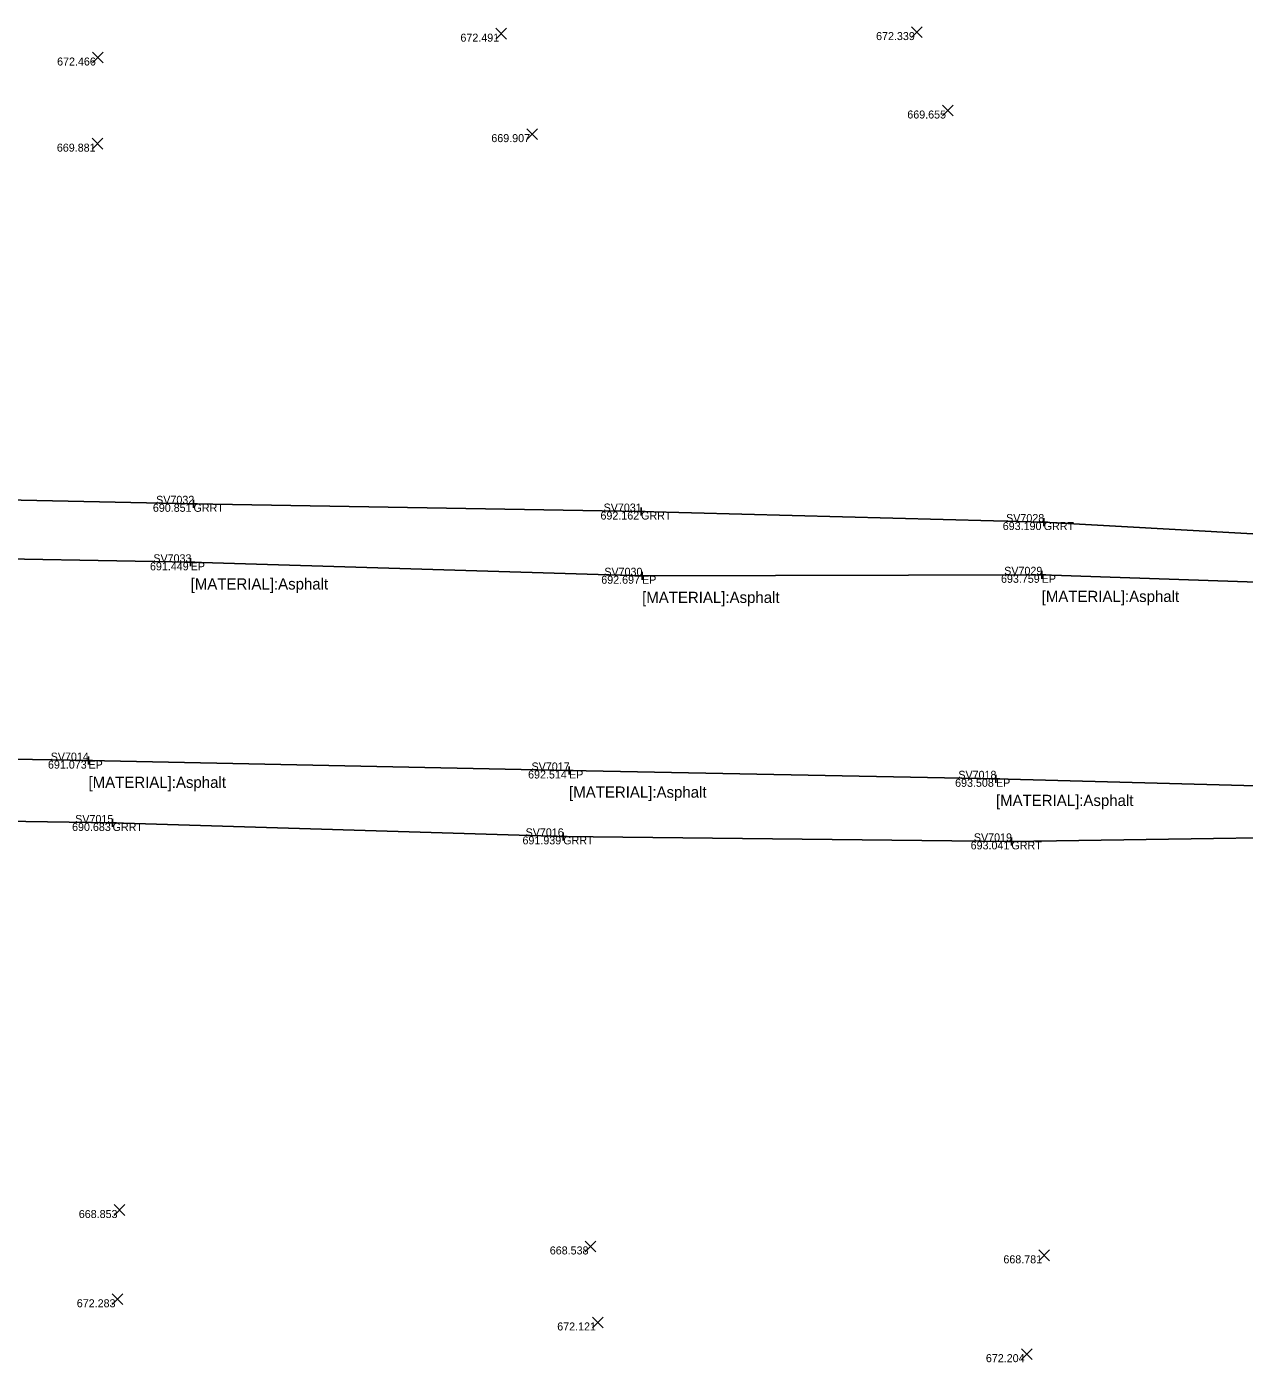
# Model space of a CAD drawing. Extents: x 1660019 to 1662995, y 619975 to 620342.
# Drawn here: x 1660960.5 to 1661112.6, y 620152.2 to 620319.1 of the extents above; entities that cross this region are included whole.
import ezdxf

# ---------------------------------------------------------------- set-up
doc = ezdxf.new("R2010")
doc.units = 0
for name, color, linetype in [('BR_X_Rail_Object', 7, 'Continuous'), ('PV_X_EOP', 7, 'Continuous'), ('RD_P_GR_Lt', 7, 'Continuous'), ('RD_P_GR_Rt', 7, 'Continuous'), ('RD_X_GR_Bar', 7, 'Continuous'), ('RD_X_GR_Rt', 7, 'Continuous'), ('RD_X_Wall', 7, 'Continuous'), ('SV_X_Text', 7, 'Continuous')]:
    doc.layers.add(name, color=color, linetype=linetype)

msp = doc.modelspace()

# ---------------------------------------------------------------- linework, layer by layer
at = {"layer": 'PV_X_EOP'}
for points in [[(1661208.92, 620246.9), (1661156.94, 620248.21), (1661087.29, 620250.6), (1661037.39, 620250.48), (1660981.01, 620252.16), (1660916.41, 620253.34), (1660855.2, 620254.44), (1660801.44, 620255.57), (1660749.64, 620256.49), (1660700.03, 620257.78), (1660643.44, 620258.64), (1660593.17, 620259.57)], [(1660597.37, 620234.1), (1660651.64, 620233.44), (1660703.42, 620232.61), (1660757.32, 620231.35), (1660809.76, 620230.12), (1660857.03, 620229.26), (1660910.07, 620228.44), (1660968.25, 620227.38), (1661028.27, 620226.15), (1661081.58, 620225.11), (1661140.41, 620223.53), (1661201.71, 620222.7)]]:
    msp.add_lwpolyline(points, dxfattribs=at)
at = {"layer": 'RD_P_GR_Lt'}
for p, q in [((1660980.87, 620259.47), (1660981.87, 620259.47)), ((1660981.37, 620259.97), (1660981.37, 620258.97)), ((1660981.37, 620259.47), (1660981.37, 620259.47)), ((1661037.26, 620259), (1661037.26, 620258)), ((1661036.76, 620258.5), (1661037.76, 620258.5)), ((1661037.26, 620258.5), (1661037.26, 620258.5)), ((1661087.04, 620257.19), (1661088.04, 620257.19)), ((1661087.54, 620257.69), (1661087.54, 620256.69)), ((1661087.54, 620257.19), (1661087.54, 620257.19)), ((1660980.51, 620252.16), (1660981.51, 620252.16)), ((1660981.01, 620252.66), (1660981.01, 620251.66)), ((1660981.01, 620252.16), (1660981.01, 620252.16)), ((1661036.89, 620250.48), (1661037.89, 620250.48)), ((1661037.39, 620250.98), (1661037.39, 620249.98)), ((1661037.39, 620250.48), (1661037.39, 620250.48)), ((1661086.79, 620250.6), (1661087.79, 620250.6)), ((1661087.29, 620251.1), (1661087.29, 620250.1)), ((1661087.29, 620250.6), (1661087.29, 620250.6)), ((1660967.75, 620227.38), (1660968.75, 620227.38)), ((1660968.25, 620227.88), (1660968.25, 620226.88)), ((1660968.25, 620227.38), (1660968.25, 620227.38)), ((1661027.77, 620226.15), (1661028.77, 620226.15)), ((1661028.27, 620226.65), (1661028.27, 620225.65)), ((1661028.27, 620226.15), (1661028.27, 620226.15)), ((1661081.58, 620225.61), (1661081.58, 620224.61)), ((1661081.08, 620225.11), (1661082.08, 620225.11)), ((1661081.58, 620225.11), (1661081.58, 620225.11)), ((1660970.76, 620219.59), (1660971.76, 620219.59)), ((1660971.26, 620220.09), (1660971.26, 620219.09)), ((1660971.26, 620219.59), (1660971.26, 620219.59)), ((1661027.04, 620217.92), (1661028.04, 620217.92)), ((1661027.54, 620218.42), (1661027.54, 620217.42)), ((1661027.54, 620217.92), (1661027.54, 620217.92)), ((1661083.01, 620217.29), (1661084.01, 620217.29)), ((1661083.51, 620217.79), (1661083.51, 620216.79)), ((1661083.51, 620217.29), (1661083.51, 620217.29))]:
    msp.add_line(p, q, dxfattribs=at)
at = {"layer": 'RD_P_GR_Rt'}
for p, q in [((1661019.12, 620317.54), (1661020.45, 620318.88)), ((1661019.12, 620318.88), (1661020.45, 620317.54)), ((1661071.03, 620317.75), (1661072.36, 620319.08)), ((1661071.03, 620319.08), (1661072.36, 620317.75)), ((1660968.77, 620314.56), (1660970.1, 620315.89)), ((1660968.77, 620315.89), (1660970.1, 620314.56)), ((1661074.92, 620307.94), (1661076.25, 620309.28)), ((1661074.92, 620309.28), (1661076.25, 620307.94)), ((1661022.99, 620304.99), (1661024.32, 620306.32)), ((1661022.99, 620306.32), (1661024.32, 620304.99)), ((1660968.71, 620303.8), (1660970.05, 620305.14)), ((1660968.71, 620305.14), (1660970.05, 620303.8)), ((1660971.44, 620170.56), (1660972.77, 620171.9)), ((1660971.44, 620171.9), (1660972.77, 620170.56)), ((1661030.29, 620166.02), (1661031.63, 620167.35)), ((1661030.29, 620167.35), (1661031.63, 620166.02)), ((1661086.92, 620164.9), (1661088.25, 620166.24)), ((1661086.92, 620166.24), (1661088.25, 620164.9)), ((1660971.19, 620159.41), (1660972.52, 620160.74)), ((1660971.19, 620160.74), (1660972.52, 620159.41)), ((1661031.2, 620156.51), (1661032.53, 620157.85)), ((1661031.2, 620157.85), (1661032.53, 620156.51)), ((1661084.78, 620152.55), (1661086.11, 620153.89)), ((1661084.78, 620153.89), (1661086.11, 620152.55))]:
    msp.add_line(p, q, dxfattribs=at)
at = {"layer": 'RD_X_GR_Rt'}
for points in [[(1661224.69, 620250.79), (1661156.18, 620253.35), (1661087.54, 620257.19), (1661037.26, 620258.5), (1660981.37, 620259.47), (1660918.68, 620260.81), (1660856.77, 620262.08), (1660800.7, 620262.74), (1660750.31, 620264.54), (1660700.27, 620265.16), (1660644.43, 620266.52), (1660592.86, 620267.53)], [(1660596.86, 620226.32), (1660650.68, 620225.81), (1660702.7, 620224.83), (1660759.05, 620223.97), (1660808.86, 620222.78), (1660856.77, 620221.69), (1660908.98, 620220.55), (1660971.26, 620219.59), (1661027.54, 620217.92), (1661083.51, 620217.29), (1661139.61, 620218.11), (1661215.13, 620218.24)]]:
    msp.add_lwpolyline(points, dxfattribs=at)

# ---------------------------------------------------------------- texts
at = {"layer": 'BR_X_Rail_Object'}
for s, p in [('GRRT', (1660981.37, 620258.47)), ('GRRT', (1661037.26, 620257.5)), ('GRRT', (1661087.54, 620256.19)), ('EP', (1660981.01, 620251.16)), ('EP', (1661037.39, 620249.48)), ('EP', (1661087.29, 620249.6)), ('EP', (1660968.25, 620226.38)), ('EP', (1661028.27, 620225.15)), ('EP', (1661081.58, 620224.11)), ('GRRT', (1660971.26, 620218.59)), ('GRRT', (1661027.54, 620216.92)), ('GRRT', (1661083.51, 620216.29))]:
    msp.add_text(s, height=1, dxfattribs=at).set_placement(p)
at = {"layer": 'RD_X_GR_Bar'}
for s, p in [('672.491', (1661014.7, 620317.21)), ('672.339', (1661066.61, 620317.41)), ('672.466', (1660964.33, 620314.23)), ('669.655', (1661070.51, 620307.61)), ('669.907', (1661018.56, 620304.66)), ('669.881', (1660964.3, 620303.47)), ('690.851', (1660976.29, 620258.47)), ('692.162', (1661032.19, 620257.5)), ('693.190', (1661082.43, 620256.19)), ('691.449', (1660975.93, 620251.16)), ('692.697', (1661032.29, 620249.48)), ('693.759', (1661082.21, 620249.6)), ('691.073', (1660963.19, 620226.38)), ('692.514', (1661023.15, 620225.15)), ('693.508', (1661076.48, 620224.11)), ('690.683', (1660966.2, 620218.59)), ('691.939', (1661022.45, 620216.92)), ('693.041', (1661078.42, 620216.29)), ('668.853', (1660967.04, 620170.23)), ('668.538', (1661025.86, 620165.68)), ('668.781', (1661082.51, 620164.57)), ('672.283', (1660966.79, 620159.08)), ('672.121', (1661026.79, 620156.18)), ('672.204', (1661080.32, 620152.22))]:
    msp.add_text(s, height=1, dxfattribs=at).set_placement(p)
at = {"layer": 'RD_X_Wall'}
for s, p in [('SV7032', (1660976.7, 620259.47)), ('SV7031', (1661032.58, 620258.5)), ('SV7028', (1661082.85, 620257.19)), ('SV7033', (1660976.35, 620252.16)), ('SV7030', (1661032.67, 620250.48)), ('SV7029', (1661082.61, 620250.6)), ('SV7014', (1660963.53, 620227.38)), ('SV7017', (1661023.58, 620226.15)), ('SV7018', (1661076.88, 620225.11)), ('SV7015', (1660966.59, 620219.59)), ('SV7016', (1661022.84, 620217.92)), ('SV7019', (1661078.82, 620217.29))]:
    msp.add_text(s, height=1, dxfattribs=at).set_placement(p)
at = {"layer": 'SV_X_Text'}
for p in [(1660981.01, 620248.76), (1661087.29, 620247.2), (1661037.39, 620247.08), (1660968.25, 620223.98), (1661028.27, 620222.75), (1661081.58, 620221.71)]:
    msp.add_text('[MATERIAL]:Asphalt', height=1.4, dxfattribs=at).set_placement(p)

doc.saveas('drawing.dxf')
